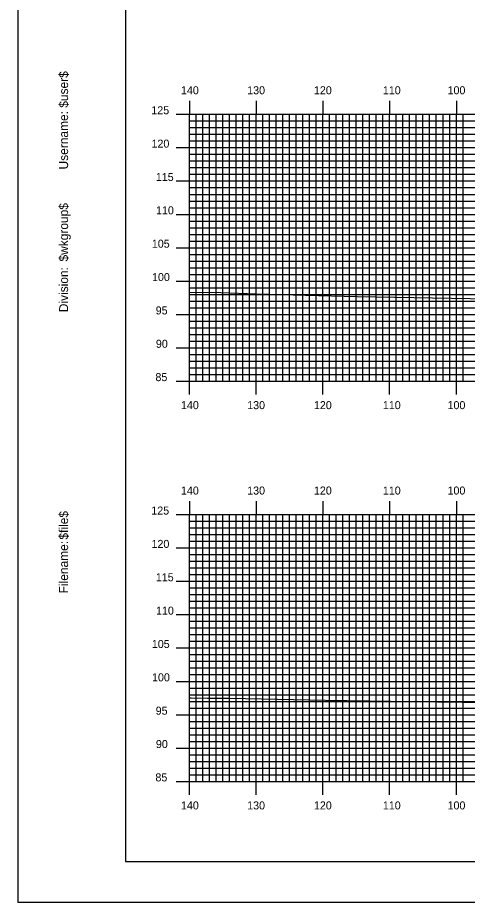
# Model space of a CAD drawing. Extents: x 1786582 to 1786926, y 442591 to 442811.
# Drawn here: x 1786582.3 to 1786649.7, y 442590.5 to 442723.1 of the extents above; entities that cross this region are included whole.
import ezdxf

# ---------------------------------------------------------------- set-up
doc = ezdxf.new("R2010")
doc.units = 0
for name, color, linetype in [('BORDER', 7, 'Continuous'), ('H_V ANNOTATION', 7, 'Continuous'), ('MAJOR', 7, 'Continuous'), ('MINOR', 7, 'Continuous'), ('PLOT BOUNDARY', 7, 'Continuous'), ('S_Roadway_Centerline', 7, 'Continuous')]:
    doc.layers.add(name, color=color, linetype=linetype)

msp = doc.modelspace()

# ---------------------------------------------------------------- linework, layer by layer
at = {"layer": 'BORDER'}
msp.add_lwpolyline([(1786598.48, 442596.67), (1786918.48, 442596.67), (1786918.48, 442806.67), (1786598.48, 442806.67)], close=True, dxfattribs=at)
at = {"layer": 'MAJOR'}
for p, q in [((1786608.08, 442710.67), (1786608.08, 442708.67)), ((1786618.08, 442710.67), (1786618.08, 442708.67)), ((1786628.08, 442710.67), (1786628.08, 442708.67)), ((1786638.08, 442710.67), (1786638.08, 442708.67)), ((1786648.08, 442710.67), (1786648.08, 442708.67)), ((1786606.07, 442708.67), (1786608.08, 442708.67)), ((1786608.08, 442708.67), (1786888.08, 442708.67)), ((1786608.08, 442668.67), (1786608.08, 442708.67)), ((1786608.08, 442668.67), (1786608.08, 442708.67)), ((1786608.08, 442708.67), (1786888.08, 442708.67)), ((1786618.08, 442668.67), (1786618.08, 442708.67)), ((1786628.08, 442668.67), (1786628.08, 442708.67)), ((1786638.08, 442668.67), (1786638.08, 442708.67)), ((1786648.08, 442668.67), (1786648.08, 442708.67)), ((1786606.07, 442703.67), (1786608.08, 442703.67)), ((1786608.08, 442703.67), (1786888.08, 442703.67)), ((1786606.07, 442698.67), (1786608.08, 442698.67)), ((1786608.08, 442698.67), (1786888.08, 442698.67)), ((1786606.07, 442693.67), (1786608.08, 442693.67)), ((1786608.08, 442693.67), (1786888.08, 442693.67)), ((1786606.07, 442688.67), (1786608.08, 442688.67)), ((1786608.08, 442688.67), (1786888.08, 442688.67)), ((1786606.07, 442683.67), (1786608.08, 442683.67)), ((1786608.08, 442683.67), (1786888.08, 442683.67)), ((1786606.07, 442678.67), (1786608.08, 442678.67)), ((1786608.08, 442678.67), (1786888.08, 442678.67)), ((1786606.07, 442673.67), (1786608.08, 442673.67)), ((1786608.08, 442673.67), (1786888.08, 442673.67)), ((1786606.07, 442668.67), (1786608.08, 442668.67)), ((1786608.08, 442668.67), (1786888.08, 442668.67)), ((1786608.08, 442668.67), (1786888.08, 442668.67)), ((1786608.08, 442666.66), (1786608.08, 442668.67)), ((1786618.08, 442666.66), (1786618.08, 442668.67)), ((1786628.08, 442666.66), (1786628.08, 442668.67)), ((1786638.08, 442666.66), (1786638.08, 442668.67)), ((1786648.08, 442666.66), (1786648.08, 442668.67)), ((1786608.08, 442650.67), (1786608.08, 442648.67)), ((1786618.08, 442650.67), (1786618.08, 442648.67)), ((1786628.08, 442650.67), (1786628.08, 442648.67)), ((1786638.08, 442650.67), (1786638.08, 442648.67)), ((1786648.08, 442650.67), (1786648.08, 442648.67)), ((1786606.07, 442648.67), (1786608.08, 442648.67)), ((1786608.08, 442648.67), (1786888.08, 442648.67)), ((1786608.08, 442608.67), (1786608.08, 442648.67)), ((1786608.08, 442608.67), (1786608.08, 442648.67)), ((1786608.08, 442648.67), (1786888.08, 442648.67)), ((1786618.08, 442608.67), (1786618.08, 442648.67)), ((1786628.08, 442608.67), (1786628.08, 442648.67)), ((1786638.08, 442608.67), (1786638.08, 442648.67)), ((1786648.08, 442608.67), (1786648.08, 442648.67)), ((1786606.07, 442643.67), (1786608.08, 442643.67)), ((1786608.08, 442643.67), (1786888.08, 442643.67)), ((1786606.07, 442638.67), (1786608.08, 442638.67)), ((1786608.08, 442638.67), (1786888.08, 442638.67)), ((1786606.07, 442633.67), (1786608.08, 442633.67)), ((1786608.08, 442633.67), (1786888.08, 442633.67)), ((1786606.07, 442628.67), (1786608.08, 442628.67)), ((1786608.08, 442628.67), (1786888.08, 442628.67)), ((1786606.07, 442623.67), (1786608.08, 442623.67)), ((1786608.08, 442623.67), (1786888.08, 442623.67)), ((1786606.07, 442618.67), (1786608.08, 442618.67)), ((1786608.08, 442618.67), (1786888.08, 442618.67)), ((1786606.07, 442613.67), (1786608.08, 442613.67)), ((1786608.08, 442613.67), (1786888.08, 442613.67)), ((1786606.07, 442608.67), (1786608.08, 442608.67)), ((1786608.08, 442608.67), (1786888.08, 442608.67)), ((1786608.08, 442608.67), (1786888.08, 442608.67)), ((1786608.08, 442606.66), (1786608.08, 442608.67)), ((1786618.08, 442606.66), (1786618.08, 442608.67)), ((1786628.08, 442606.66), (1786628.08, 442608.67)), ((1786638.08, 442606.66), (1786638.08, 442608.67)), ((1786648.08, 442606.66), (1786648.08, 442608.67))]:
    msp.add_line(p, q, dxfattribs=at)
at = {"layer": 'MINOR'}
for p, q in [((1786609.08, 442668.67), (1786609.08, 442708.67)), ((1786610.08, 442668.67), (1786610.08, 442708.67)), ((1786611.08, 442668.67), (1786611.08, 442708.67)), ((1786612.08, 442668.67), (1786612.08, 442708.67)), ((1786613.08, 442668.67), (1786613.08, 442708.67)), ((1786614.08, 442668.67), (1786614.08, 442708.67)), ((1786615.08, 442668.67), (1786615.08, 442708.67)), ((1786616.08, 442668.67), (1786616.08, 442708.67)), ((1786617.08, 442668.67), (1786617.08, 442708.67)), ((1786619.08, 442668.67), (1786619.08, 442708.67)), ((1786620.08, 442668.67), (1786620.08, 442708.67)), ((1786621.08, 442668.67), (1786621.08, 442708.67)), ((1786622.08, 442668.67), (1786622.08, 442708.67)), ((1786623.08, 442668.67), (1786623.08, 442708.67)), ((1786624.08, 442668.67), (1786624.08, 442708.67)), ((1786625.08, 442668.67), (1786625.08, 442708.67)), ((1786626.08, 442668.67), (1786626.08, 442708.67)), ((1786627.08, 442668.67), (1786627.08, 442708.67)), ((1786629.08, 442668.67), (1786629.08, 442708.67)), ((1786630.08, 442668.67), (1786630.08, 442708.67)), ((1786631.08, 442668.67), (1786631.08, 442708.67)), ((1786632.08, 442668.67), (1786632.08, 442708.67)), ((1786633.08, 442668.67), (1786633.08, 442708.67)), ((1786634.08, 442668.67), (1786634.08, 442708.67)), ((1786635.08, 442668.67), (1786635.08, 442708.67)), ((1786636.08, 442668.67), (1786636.08, 442708.67)), ((1786637.08, 442668.67), (1786637.08, 442708.67)), ((1786639.08, 442668.67), (1786639.08, 442708.67)), ((1786640.08, 442668.67), (1786640.08, 442708.67)), ((1786641.08, 442668.67), (1786641.08, 442708.67)), ((1786642.08, 442668.67), (1786642.08, 442708.67)), ((1786643.08, 442668.67), (1786643.08, 442708.67)), ((1786644.08, 442668.67), (1786644.08, 442708.67)), ((1786645.08, 442668.67), (1786645.08, 442708.67)), ((1786646.08, 442668.67), (1786646.08, 442708.67)), ((1786647.08, 442668.67), (1786647.08, 442708.67)), ((1786649.08, 442668.67), (1786649.08, 442708.67)), ((1786608.08, 442707.67), (1786888.08, 442707.67)), ((1786608.08, 442707.67), (1786610.08, 442707.67)), ((1786608.08, 442706.67), (1786888.08, 442706.67)), ((1786608.08, 442706.67), (1786610.08, 442706.67)), ((1786608.08, 442705.67), (1786888.08, 442705.67)), ((1786608.08, 442705.67), (1786610.08, 442705.67)), ((1786608.08, 442704.67), (1786888.08, 442704.67)), ((1786608.08, 442704.67), (1786610.08, 442704.67)), ((1786608.08, 442702.67), (1786888.08, 442702.67)), ((1786608.08, 442702.67), (1786610.08, 442702.67)), ((1786608.08, 442701.67), (1786888.08, 442701.67)), ((1786608.08, 442701.67), (1786610.08, 442701.67)), ((1786608.08, 442700.67), (1786888.08, 442700.67)), ((1786608.08, 442700.67), (1786610.08, 442700.67)), ((1786608.08, 442699.67), (1786888.08, 442699.67)), ((1786608.08, 442699.67), (1786610.08, 442699.67)), ((1786608.08, 442697.67), (1786888.08, 442697.67)), ((1786608.08, 442697.67), (1786610.08, 442697.67)), ((1786608.08, 442696.67), (1786888.08, 442696.67)), ((1786608.08, 442696.67), (1786610.08, 442696.67)), ((1786608.08, 442695.67), (1786888.08, 442695.67)), ((1786608.08, 442695.67), (1786610.08, 442695.67)), ((1786608.08, 442694.67), (1786888.08, 442694.67)), ((1786608.08, 442694.67), (1786610.08, 442694.67)), ((1786608.08, 442692.67), (1786888.08, 442692.67)), ((1786608.08, 442692.67), (1786610.08, 442692.67)), ((1786608.08, 442691.67), (1786888.08, 442691.67)), ((1786608.08, 442691.67), (1786610.08, 442691.67)), ((1786608.08, 442690.67), (1786888.08, 442690.67)), ((1786608.08, 442690.67), (1786610.08, 442690.67)), ((1786608.08, 442689.67), (1786888.08, 442689.67)), ((1786608.08, 442689.67), (1786610.08, 442689.67)), ((1786608.08, 442687.67), (1786888.08, 442687.67)), ((1786608.08, 442687.67), (1786610.08, 442687.67)), ((1786608.08, 442686.67), (1786888.08, 442686.67)), ((1786608.08, 442686.67), (1786610.08, 442686.67)), ((1786608.08, 442685.67), (1786888.08, 442685.67)), ((1786608.08, 442685.67), (1786610.08, 442685.67)), ((1786608.08, 442684.67), (1786888.08, 442684.67)), ((1786608.08, 442684.67), (1786610.08, 442684.67)), ((1786608.08, 442682.67), (1786888.08, 442682.67)), ((1786608.08, 442682.67), (1786610.08, 442682.67)), ((1786608.08, 442681.67), (1786888.08, 442681.67)), ((1786608.08, 442681.67), (1786610.08, 442681.67)), ((1786608.08, 442680.67), (1786888.08, 442680.67)), ((1786608.08, 442680.67), (1786610.08, 442680.67)), ((1786608.08, 442679.67), (1786888.08, 442679.67)), ((1786608.08, 442679.67), (1786610.08, 442679.67)), ((1786608.08, 442677.67), (1786888.08, 442677.67)), ((1786608.08, 442677.67), (1786610.08, 442677.67)), ((1786608.08, 442676.67), (1786888.08, 442676.67)), ((1786608.08, 442676.67), (1786610.08, 442676.67)), ((1786608.08, 442675.67), (1786888.08, 442675.67)), ((1786608.08, 442675.67), (1786610.08, 442675.67)), ((1786608.08, 442674.67), (1786888.08, 442674.67)), ((1786608.08, 442674.67), (1786610.08, 442674.67)), ((1786608.08, 442672.67), (1786888.08, 442672.67)), ((1786608.08, 442672.67), (1786610.08, 442672.67)), ((1786608.08, 442671.67), (1786888.08, 442671.67)), ((1786608.08, 442671.67), (1786610.08, 442671.67)), ((1786608.08, 442670.67), (1786888.08, 442670.67)), ((1786608.08, 442670.67), (1786610.08, 442670.67)), ((1786608.08, 442669.67), (1786888.08, 442669.67)), ((1786608.08, 442669.67), (1786610.08, 442669.67)), ((1786609.08, 442608.67), (1786609.08, 442648.67)), ((1786610.08, 442608.67), (1786610.08, 442648.67)), ((1786611.08, 442608.67), (1786611.08, 442648.67)), ((1786612.08, 442608.67), (1786612.08, 442648.67)), ((1786613.08, 442608.67), (1786613.08, 442648.67)), ((1786614.08, 442608.67), (1786614.08, 442648.67)), ((1786615.08, 442608.67), (1786615.08, 442648.67)), ((1786616.08, 442608.67), (1786616.08, 442648.67)), ((1786617.08, 442608.67), (1786617.08, 442648.67)), ((1786619.08, 442608.67), (1786619.08, 442648.67)), ((1786620.08, 442608.67), (1786620.08, 442648.67)), ((1786621.08, 442608.67), (1786621.08, 442648.67)), ((1786622.08, 442608.67), (1786622.08, 442648.67)), ((1786623.08, 442608.67), (1786623.08, 442648.67)), ((1786624.08, 442608.67), (1786624.08, 442648.67)), ((1786625.08, 442608.67), (1786625.08, 442648.67)), ((1786626.08, 442608.67), (1786626.08, 442648.67)), ((1786627.08, 442608.67), (1786627.08, 442648.67)), ((1786629.08, 442608.67), (1786629.08, 442648.67)), ((1786630.08, 442608.67), (1786630.08, 442648.67)), ((1786631.08, 442608.67), (1786631.08, 442648.67)), ((1786632.08, 442608.67), (1786632.08, 442648.67)), ((1786633.08, 442608.67), (1786633.08, 442648.67)), ((1786634.08, 442608.67), (1786634.08, 442648.67)), ((1786635.08, 442608.67), (1786635.08, 442648.67)), ((1786636.08, 442608.67), (1786636.08, 442648.67)), ((1786637.08, 442608.67), (1786637.08, 442648.67)), ((1786639.08, 442608.67), (1786639.08, 442648.67)), ((1786640.08, 442608.67), (1786640.08, 442648.67)), ((1786641.08, 442608.67), (1786641.08, 442648.67)), ((1786642.08, 442608.67), (1786642.08, 442648.67)), ((1786643.08, 442608.67), (1786643.08, 442648.67)), ((1786644.08, 442608.67), (1786644.08, 442648.67)), ((1786645.08, 442608.67), (1786645.08, 442648.67)), ((1786646.08, 442608.67), (1786646.08, 442648.67)), ((1786647.08, 442608.67), (1786647.08, 442648.67)), ((1786649.08, 442608.67), (1786649.08, 442648.67)), ((1786608.08, 442647.67), (1786888.08, 442647.67)), ((1786608.08, 442647.67), (1786610.08, 442647.67)), ((1786608.08, 442646.67), (1786888.08, 442646.67)), ((1786608.08, 442646.67), (1786610.08, 442646.67)), ((1786608.08, 442645.67), (1786888.08, 442645.67)), ((1786608.08, 442645.67), (1786610.08, 442645.67)), ((1786608.08, 442644.67), (1786888.08, 442644.67)), ((1786608.08, 442644.67), (1786610.08, 442644.67)), ((1786608.08, 442642.67), (1786888.08, 442642.67)), ((1786608.08, 442642.67), (1786610.08, 442642.67)), ((1786608.08, 442641.67), (1786888.08, 442641.67)), ((1786608.08, 442641.67), (1786610.08, 442641.67)), ((1786608.08, 442640.67), (1786888.08, 442640.67)), ((1786608.08, 442640.67), (1786610.08, 442640.67)), ((1786608.08, 442639.67), (1786888.08, 442639.67)), ((1786608.08, 442639.67), (1786610.08, 442639.67)), ((1786608.08, 442637.67), (1786888.08, 442637.67)), ((1786608.08, 442637.67), (1786610.08, 442637.67)), ((1786608.08, 442636.67), (1786888.08, 442636.67)), ((1786608.08, 442636.67), (1786610.08, 442636.67)), ((1786608.08, 442635.67), (1786888.08, 442635.67)), ((1786608.08, 442635.67), (1786610.08, 442635.67)), ((1786608.08, 442634.67), (1786888.08, 442634.67)), ((1786608.08, 442634.67), (1786610.08, 442634.67)), ((1786608.08, 442632.67), (1786888.08, 442632.67)), ((1786608.08, 442632.67), (1786610.08, 442632.67)), ((1786608.08, 442631.67), (1786888.08, 442631.67)), ((1786608.08, 442631.67), (1786610.08, 442631.67)), ((1786608.08, 442630.67), (1786888.08, 442630.67)), ((1786608.08, 442630.67), (1786610.08, 442630.67)), ((1786608.08, 442629.67), (1786888.08, 442629.67)), ((1786608.08, 442629.67), (1786610.08, 442629.67)), ((1786608.08, 442627.67), (1786888.08, 442627.67)), ((1786608.08, 442627.67), (1786610.08, 442627.67)), ((1786608.08, 442626.67), (1786888.08, 442626.67)), ((1786608.08, 442626.67), (1786610.08, 442626.67)), ((1786608.08, 442625.67), (1786888.08, 442625.67)), ((1786608.08, 442625.67), (1786610.08, 442625.67)), ((1786608.08, 442624.67), (1786888.08, 442624.67)), ((1786608.08, 442624.67), (1786610.08, 442624.67)), ((1786608.08, 442622.67), (1786888.08, 442622.67)), ((1786608.08, 442622.67), (1786610.08, 442622.67)), ((1786608.08, 442621.67), (1786888.08, 442621.67)), ((1786608.08, 442621.67), (1786610.08, 442621.67)), ((1786608.08, 442620.67), (1786888.08, 442620.67)), ((1786608.08, 442620.67), (1786610.08, 442620.67)), ((1786608.08, 442619.67), (1786888.08, 442619.67)), ((1786608.08, 442619.67), (1786610.08, 442619.67)), ((1786608.08, 442617.67), (1786888.08, 442617.67)), ((1786608.08, 442617.67), (1786610.08, 442617.67)), ((1786608.08, 442616.67), (1786888.08, 442616.67)), ((1786608.08, 442616.67), (1786610.08, 442616.67)), ((1786608.08, 442615.67), (1786888.08, 442615.67)), ((1786608.08, 442615.67), (1786610.08, 442615.67)), ((1786608.08, 442614.67), (1786888.08, 442614.67)), ((1786608.08, 442614.67), (1786610.08, 442614.67)), ((1786608.08, 442612.67), (1786888.08, 442612.67)), ((1786608.08, 442612.67), (1786610.08, 442612.67)), ((1786608.08, 442611.67), (1786888.08, 442611.67)), ((1786608.08, 442611.67), (1786610.08, 442611.67)), ((1786608.08, 442610.67), (1786888.08, 442610.67)), ((1786608.08, 442610.67), (1786610.08, 442610.67)), ((1786608.08, 442609.67), (1786888.08, 442609.67)), ((1786608.08, 442609.67), (1786610.08, 442609.67))]:
    msp.add_line(p, q, dxfattribs=at)
at = {"layer": 'PLOT BOUNDARY'}
msp.add_lwpolyline([(1786582.29, 442590.55), (1786922.29, 442590.55), (1786922.29, 442810.55), (1786582.29, 442810.55)], close=True, dxfattribs=at)
at = {"layer": 'S_Roadway_Centerline'}
for points in [[(1786608.08, 442682.03), (1786612.75, 442681.96), (1786618.09, 442681.75), (1786625.46, 442681.55), (1786633.23, 442681.35), (1786653.02, 442680.99), (1786653.17, 442680.99), (1786653.29, 442680.98), (1786654.05, 442680.96), (1786673.88, 442680.33), (1786676.91, 442680.21), (1786681.1, 442680.04), (1786688.53, 442679.81), (1786694.01, 442679.56), (1786700.51, 442679.34), (1786709.11, 442679.21), (1786711.98, 442679.2), (1786714.12, 442679.12), (1786728.66, 442678.82)], [(1786608.08, 442621.22), (1786608.31, 442621.22), (1786610.74, 442621.15), (1786614.04, 442621.13), (1786628.44, 442620.87), (1786641.57, 442620.64), (1786648.97, 442620.55), (1786669.14, 442620.13), (1786669.16, 442620.13), (1786669.17, 442620.13), (1786680.9, 442619.76), (1786689.69, 442619.52), (1786692.81, 442619.46), (1786696.92, 442619.35), (1786710.05, 442619.04), (1786724.45, 442618.91)]]:
    msp.add_lwpolyline(points, dxfattribs=at)

# ---------------------------------------------------------------- texts
at = {"layer": 'BORDER'}
for s, p in [('$user$', (1786589.85, 442709.65)), ('Username:', (1786589.85, 442700.4)), ('$wkgroup$', (1786589.85, 442686.6)), ('Division:', (1786589.85, 442679)), ('$file$', (1786589.85, 442644.92)), ('Filename:', (1786589.85, 442636.86))]:
    msp.add_text(s, height=1.339, rotation=90, dxfattribs=at).set_placement(p)
at = {"layer": 'H_V ANNOTATION'}
for s, p in [('140', (1786606.78, 442711.67)), ('130', (1786616.71, 442711.67)), ('120', (1786626.72, 442711.67)), ('110', (1786637.06, 442711.67)), ('100', (1786646.76, 442711.67)), ('125', (1786602.33, 442708.67)), ('120', (1786602.36, 442703.67)), ('115', (1786603.01, 442698.67)), ('110', (1786603.04, 442693.67)), ('105', (1786602.41, 442688.67)), ('100', (1786602.44, 442683.67)), ('95', (1786602.99, 442678.67)), ('90', (1786603.02, 442673.67)), ('85', (1786602.95, 442668.67)), ('140', (1786606.78, 442664.47)), ('130', (1786616.71, 442664.47)), ('120', (1786626.72, 442664.47)), ('110', (1786637.06, 442664.47)), ('100', (1786646.76, 442664.47)), ('140', (1786606.78, 442651.67)), ('130', (1786616.71, 442651.67)), ('120', (1786626.72, 442651.67)), ('110', (1786637.06, 442651.67)), ('100', (1786646.76, 442651.67)), ('125', (1786602.33, 442648.67)), ('120', (1786602.36, 442643.67)), ('115', (1786603.01, 442638.67)), ('110', (1786603.04, 442633.67)), ('105', (1786602.41, 442628.67)), ('100', (1786602.44, 442623.67)), ('95', (1786602.99, 442618.67)), ('90', (1786603.02, 442613.67)), ('85', (1786602.95, 442608.67)), ('140', (1786606.78, 442604.47)), ('130', (1786616.71, 442604.47)), ('120', (1786626.72, 442604.47)), ('110', (1786637.06, 442604.47)), ('100', (1786646.76, 442604.47))]:
    msp.add_text(s, height=1.2, dxfattribs=at).set_placement(p)
at = {"layer": 'MAJOR'}
for p in [(1786608.07, 442668.67), (1786608.07, 442608.67)]:
    msp.add_text('-', height=0.012, dxfattribs=at).set_placement(p)

doc.saveas('drawing.dxf')
